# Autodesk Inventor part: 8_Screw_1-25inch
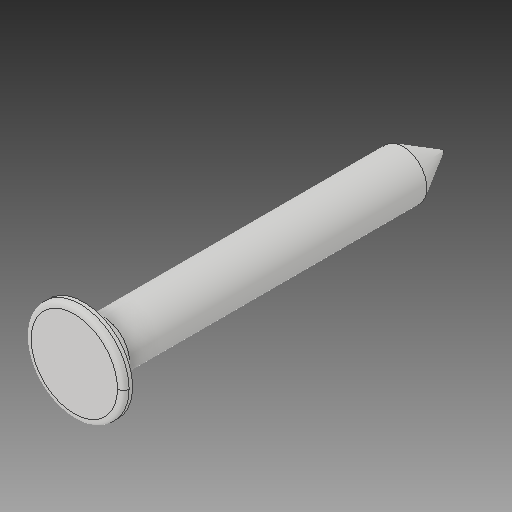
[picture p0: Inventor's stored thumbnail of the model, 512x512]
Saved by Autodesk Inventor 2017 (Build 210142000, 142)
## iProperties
Created: 2017-05
Part Number: 8_Screw_1-25inch
Material: Generic
Document SubType Name: Modeling
Designer: Savy
Density: 1 g/cm^3
Appearance: Default
Author: Savy
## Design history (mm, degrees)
feature "SOLID1"
body "Solid1"
